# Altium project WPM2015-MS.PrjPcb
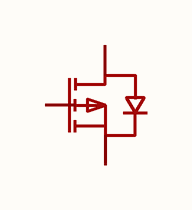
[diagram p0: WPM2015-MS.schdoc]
1 sheet, 1 parts. Net scope: global (net labels, ports and power ports of the same name join across sheets).

## Sheet WPM2015-MS.schdoc
size 127 x 101 mm

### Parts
Q?  wpm2015-ms  [SOT-23-3_L2.9-W1.3-P1.90-LS2.4-BR]  (value not drawn)

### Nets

Not connected (* = marked no-connect by the designer): Q? 1(G) 2(S) 3(D)

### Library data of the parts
Q? = wpm2015-ms: 数量:1个P沟道;漏源电压(Vdss):20V;连续漏极电流(Id):3A;导通电阻(RDS(on)):80mΩ@4.5V；110mΩ@2.5V;耗散功率(Pd):400mW;阈值电压(Vgs(th)):1V;; Manufacturer: MSKSEMI(美森科); AddInBom: yes; ModelId: c62791f0466c4ae2a892c056b845b0ca; ModelName: SOT-23-3P_L2.9-W1.3-H1.0-LS2.4-P0.95; ModelTransform: 98.425,114.173,0,180,0,0,0.0005,-0.0005,0; Number: 1个P沟道; Drain to Source Voltage: 20V; Current - Continuous Drain(Id): 3A; Pd - Power Dissipation: 400mW; Gate Threshold Voltage (Vgs(th)): 1V; Gate Charge(Qg): 5.5nC@4.5V；6nC@2.5V; Input Capacitance(Ciss): 405pF; Reverse Transfer Capacitance (Crss@Vds): 55pF; Type: P沟道; Output Capacitance(Coss): 75pF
